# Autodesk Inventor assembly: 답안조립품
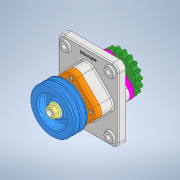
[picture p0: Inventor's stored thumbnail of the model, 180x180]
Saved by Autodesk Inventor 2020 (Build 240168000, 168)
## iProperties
Created: 2021-07
Part Number: 답안조립품
Document SubType Name: Assembly
Designer: Owner
Author: Owner
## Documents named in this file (16)
- C:\Users\Owner\Desktop\710707V1012\710707V1012\답안조립품.iam
- C:\Users\Owner\Desktop\710707V1012\710707V1012\본체.ipt
- C:\Users\Owner\Desktop\710707V1012\710707V1012\M16 너트.ipt
- C:\Users\Owner\Desktop\710707V1012\710707V1012\V-벨트풀리.ipt
- C:\Users\Owner\Desktop\710707V1012\710707V1012\멈춤나사 M4.ipt
- C:\Users\Owner\Desktop\710707V1012\710707V1012\베어링 6206.ipt
- C:\Users\Owner\Desktop\710707V1012\710707V1012\볼트 M6.ipt
- C:\Users\Owner\Desktop\710707V1012\710707V1012\부시.ipt
- C:\Users\Owner\Desktop\710707V1012\710707V1012\오일실 30x42x8.ipt
- C:\Users\Owner\Desktop\710707V1012\710707V1012\오일실 30x45x8.ipt
- C:\Users\Owner\Desktop\710707V1012\710707V1012\체인 스프로킷.ipt
- C:\Users\Owner\Desktop\710707V1012\710707V1012\축.ipt
- C:\Users\Owner\Desktop\710707V1012\710707V1012\커버A.ipt
- C:\Users\Owner\Desktop\710707V1012\710707V1012\커버B.ipt
- C:\Users\Owner\Desktop\710707V1012\710707V1012\키 6x6x18.ipt
- C:\Users\Owner\Desktop\710707V1012\710707V1012\키 6x6x20.ipt
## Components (3 placed, 2 different names)
1. M16 너트:1 — 각도:1
2. V-벨트풀리:1
3. M16 너트:2 — 각도:2
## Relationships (2: Angle 2)
- 각도:1 [Angle]: M16 너트:1
- 각도:2 [Angle]: M16 너트:2
